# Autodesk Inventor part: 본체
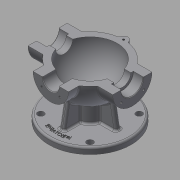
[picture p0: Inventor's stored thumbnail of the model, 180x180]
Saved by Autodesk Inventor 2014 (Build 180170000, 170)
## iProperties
Created: 2015-12
Part Number: 본체
Material: 알루미늄 6061
Document SubType Name: Modeling
Designer: mduedu
Density: 1 g/cm^3
Appearance: 알루미늄 - 평지
Author: mduedu
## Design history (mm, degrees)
sketch "스케치1"
  geometry: L1 (-53, 0)-(53, 0); A1 r 53 centre (0, 0) between (53, 0) and (-53, 0); 2 further points
  constraints: 2 coincident, 2 end point, 2 point on circle, 1 centre point, 1 horizontal, 1 midpoint
  dimensions: "d0" = 53 radius of A1
revolve "회전1" sketch "스케치1" stored, may be unused: angle "d2" = 90 deg
feature "쉘1" dims "d11" = 10
node "작업 평면1"
sketch "스케치2"
  geometry: C1 r 31 at (0, 0); 1 further point
  constraints: 1 centre point, 1 coincident
  dimensions: "d4" = 62 diameter of C1
extrude "돌출1" join sketch "스케치2" stored distance "d5" = 10; taper "d6" = 0 deg
node "작업 평면2"
sketch "스케치3"
  geometry: C1 r 28 at (0, 0); 1 further point
  constraints: 1 centre point, 1 coincident
  dimensions: "d8" = 56 diameter of C1
extrude "돌출2" join sketch "스케치3" stored distance "d9" = 10; taper "d10" = 0 deg
hole "구멍1" diameter "d14" = 35; stored, may be unused: countersink angle "d18" = 90 deg, drill point angle "d20" = 0 deg; dims "d12" = 10, "d13" = 10, "d15" = 6, "d16" = 4, "d17" = 2, "d19" = 16
hole "구멍2" diameter "d23" = 27; stored, may be unused: countersink angle "d27" = 90 deg, drill point angle "d29" = 0 deg; dims "d21" = 10, "d22" = 10, "d24" = 6, "d25" = 4, "d26" = 2, "d28" = 16
fillet "모깎기1" dims "d30" = 0.3
hole "구멍3" diameter "d33" = 26; stored, may be unused: countersink angle "d37" = 90 deg, drill point angle "d39" = 0 deg; dims "d31" = 10, "d32" = 10, "d34" = 6, "d35" = 4, "d36" = 2, "d38" = 16
chamfer "모따기1" distance "d40" = 1; stored, may be unused: second distance "d41" = 2, angle "d42" = 45 deg
sketch "스케치4"
  geometry: L1 (0, 0)-(0, -25); L2 (0, 0)-(-17.678, -17.678); A1 r 25 centre (0, 0) between (-17.678, -17.678) and (0, -25); 1 further point
  constraints: 4 end point, 2 point on circle, 1 centre point, 1 coincident, 1 vertical
  dimensions: "d43" = 50 diameter of A1; "d47" = 45 deg angle of L1 L2
hole "구멍4" sketch "스케치4" at (-17.678, -17.678) diameter "d49" = 3.242; stored, may be unused: countersink angle "d53" = 90 deg, drill point angle "d55" = 118 deg; dims "d50" = 11, "d51" = 4, "d52" = 2, "d54" = 13
sketch "스케치5"
  geometry: L1 (0, 0)-(0, -20); L2 (0, 0)-(-14.142, -14.142); A1 r 20 centre (0, 0) between (0, -20) and (-14.142, -14.142); 2 further points
  constraints: 4 end point, 2 coincident, 2 point on circle, 1 centre point, 1 vertical
  dimensions: "d59" = 40 diameter of A1; "d65" = 45 deg angle of L1 L2
hole "구멍5" sketch "스케치5" at (-14.142, -14.142) diameter "d67" = 3.242; stored, may be unused: countersink angle "d71" = 90 deg, drill point angle "d73" = 118 deg; dims "d68" = 8, "d69" = 4, "d70" = 2, "d72" = 10
node "작업 평면3"
sketch "스케치6"
  geometry: C1 r 65 at (0, 0); 1 further point
  constraints: 1 centre point, 1 coincident
  dimensions: "d78" = 130 diameter of C1
extrude "돌출3" join sketch "스케치6" distance "d80" = 10; taper "d81" = 0 deg
sketch "스케치7"
  geometry: C1 r 20 at (0, 0); 1 further point
  constraints: 1 centre point, 1 coincident
  dimensions: "d82" = 40 diameter of C1
extrude "돌출4" join sketch "스케치7" stored distance "d84" = 10; taper "d85" = 0 deg
sketch "스케치8"
  geometry: 2 further points
  constraints: 1 coincident
hole "구멍6" sketch "스케치8" at (0, 0) diameter "d86" = 20; stored, may be unused: countersink angle "d90" = 90 deg, drill point angle "d92" = 118 deg; dims "d87" = 7, "d88" = 40, "d89" = 5, "d91" = 10
fillet "모깎기2" dims "d93" = 0.3
sketch "스케치9"
  geometry: L1 (65, -75)-(-65, -75) reference; L2 (-45, -75)-(-38.245, -36.692); A1 r 53 centre (0, 0) between (42.988, 31) and (42.988, -31) reference; 1 further point
  constraints: 2 end point, 1 point on circle, 1 point on line
  dimensions: "d94" = 45 horizontal distance of L2.start point (0, 0); "d95" = 80 deg angle of L2 L1
feature "리브1" sketch "스케치9" dims "d96" = 1, "d97" = 8, "d98" = 0, "d99" = 0, "d100" = 1, "d101" = 1
sketch "스케치10"
  geometry: L1 (0, 0)-(0, -55); L2 (0, 0)-(-38.891, -38.891); A1 r 55 centre (0, 0) between (0, -55) and (-38.891, -38.891); 2 further points
  constraints: 4 end point, 2 coincident, 2 point on circle, 1 centre point, 1 vertical
  dimensions: "d105" = 110 diameter of A1; "d107" = 45 deg angle of L1 L2
hole "구멍7" sketch "스케치10" at (-38.891, -38.891) diameter "d109" = 10; stored, may be unused: countersink angle "d113" = 90 deg, drill point angle "d115" = 118 deg; dims "d110" = 7, "d111" = 40, "d112" = 5, "d114" = 10
fillet "모깎기3" dims "d120" = 3
fillet "모깎기4" dims "d121" = 3, "d122" = 3
fillet "모깎기5" dims "d123" = 3
fillet "모깎기6" dims "d124" = 3
sketch "스케치11"
  geometry: C1 r 5 at (-38.891, 38.891) reference; C2 r 5 at (38.891, 38.891) reference; C3 r 5 at (38.891, -38.891) reference; C4 r 5 at (-38.891, -38.891) reference; C5 r 20 at (0, 0) reference; C6 r 65 at (0, 0) reference; 1 further point
  constraints: 3 other
feature "엠보싱1" sketch "스케치11" dims "d125" = 0.5, "d126" = 0
sketch "스케치12"
  geometry: L1 (0, 100)-(0, -100); L2 (0, 100)-(100, 100); L3 (100, 100)-(100, -100); L4 (100, -100)-(0, -100); 2 further points
  constraints: 8 end point, 3 perpendicular, 1 coincident, 1 midpoint, 1 vertical
  dimensions: "d127" = 200 distance of L2.end L3.end; "d129" = 100 distance between parallel lines of L1 L3
extrude "돌출5" cut sketch "스케치12" stored distance "d130" = 10; taper "d131" = 0 deg
sketch "스케치13"
  geometry: C1 r 7 at (0, 53); A1 r 53 centre (0, 0) between (42.113, 32.179) and (-42.113, 32.179) reference; 1 further point
  constraints: 1 centre point, 1 point on circle
  dimensions: "d132" = 14 diameter of C1
extrude "돌출6" join sketch "스케치13" distance "d134" = 15; taper "d135" = 0 deg
hole "구멍8" diameter "d139" = 3.242; stored, may be unused: countersink angle "d143" = 90 deg, drill point angle "d145" = 118 deg; dims "d140" = 8, "d141" = 4, "d142" = 2, "d144" = 10, "d148" = 10, "d149" = 10
fillet "모깎기7" dims "d146" = 3
fillet "모깎기8" dims "d147" = 3
node "솔리드1"
mirror "대칭1"
mirror "대칭2"
pattern_circular "원형 패턴1" dims angle "d57" = 360 deg
mirror "대칭3"
pattern_circular "원형 패턴2" dims angle "d75" = 360 deg
pattern_circular "원형 패턴3" dims angle "d103" = 360 deg
pattern_circular "원형 패턴4" dims angle "d118" = 360 deg
node "투영된 루프1"
other parameters: "d3" = 67, "d7" = 62, "d77" = -85
